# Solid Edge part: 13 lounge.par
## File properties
Author: Henri
Template: Normal.par
Last saved by: Henri
Revision: 5
Application: Solid Edge
Accuracy: 0,990
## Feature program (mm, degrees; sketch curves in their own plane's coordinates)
sketch for "unnamed Protrusion 1" plane through (0, 0, 0) normal (0, 0, 1) x-axis (1, 0, 0)
  line (82.5, -87.5) -> (-82.5, -87.5)
  line (-82.5, -87.5) -> (-82.5, 87.5)
  line (-82.5, 87.5) -> (82.5, 87.5)
  line (82.5, 87.5) -> (82.5, -87.5)
extrude "unnamed Protrusion 1" add finite 2.5 along -normal
sketch for "unnamed Cutout 1" plane through (0, 0, 0) normal (0, 0, 1) x-axis (1, 0, 0)
  line (-64, 72.5) -> (-45, 72.5)
  arc centre (-45, 83) radius 10.5 from (-45, 72.5) to (-34.5, 83) ccw
  line (-34.5, 83) -> (-34.5, 92)
  arc centre (-45, 92) radius 10.5 from (-34.5, 92) to (-45, 102.5) ccw
  line (-45, 102.5) -> (-64, 102.5)
  arc centre (-64, 92) radius 10.5 from (-64, 102.5) to (-74.5, 92) ccw
  line (-74.5, 92) -> (-74.5, 83)
  arc centre (-64, 83) radius 10.5 from (-74.5, 83) to (-64, 72.5) ccw
extrude "unnamed Cutout 1" cut through along -normal
sketch for "ExtrudedProtrusion_2" plane through (0, 0, 0) normal (0, 0, 1) x-axis (0, 1, 0)
  line (-87.5, -2.5) -> (-57.5, -2.5)
  arc centre (-57.5, -7.5) radius 5 from (-57.5, -2.5) to (-52.5, -7.5) cw
  line (-52.5, -7.5) -> (-52.5, -42.5)
  line (-52.5, -42.5) -> (-47.5, -47.5)
  line (-47.5, -47.5) -> (47.5, -47.5)
  line (52.5, -42.5) -> (47.5, -47.5)
  line (52.5, -42.5) -> (52.5, 22.5)
  arc centre (57.5, 22.5) radius 5 from (52.5, 22.5) to (57.5, 27.5) cw
  line (82.5, 27.5) -> (57.5, 27.5)
  arc centre (82.5, 22.5) radius 5 from (82.5, 27.5) to (87.5, 22.5) cw
  line (87.5, 22.5) -> (87.5, -82.5)
  line (-87.5, -82.5) -> (87.5, -82.5)
  line (-87.5, -2.5) -> (-87.5, -82.5)
extrude "ExtrudedProtrusion_2" add finite 37.5 along +normal
sketch for "ExtrudedCutout_2" plane through (27.5, 0, 37.5) normal (0, 0, 1) x-axis (0, 1, 0)
  line (77.5, 40) -> (77.5, -25.3553)
  line (57.8553, -45) -> (77.5, -25.3553)
  line (57.8553, -45) -> (-57.8553, -45)
  line (-77.5, -25.3553) -> (-57.8553, -45)
  line (-77.5, -25.3553) -> (-77.5, 10)
  arc centre (-72.5, 10) radius 5 from (-77.5, 10) to (-72.5, 15) cw
  line (-72.5, 15) -> (-50, 15)
  line (-50, 15) -> (-50, -13.9645)
  line (-50, -13.9645) -> (-46.4645, -17.5)
  line (-46.4645, -17.5) -> (46.4645, -17.5)
  line (46.4645, -17.5) -> (50, -13.9645)
  line (50, -13.9645) -> (50, 45)
  line (50, 45) -> (72.5, 45)
  arc centre (72.5, 40) radius 5 from (72.5, 45) to (77.5, 40) cw
extrude "ExtrudedCutout_2" cut finite 17.5 along -normal
fillet "Round_1" radius 2.5
sketch for "ExtrudedProtrusion_3" plane through (0, 0, 35) normal (0, 0, 1) x-axis (1, 0, 0)
  line (7.5, -37.5) -> (7.5, 7.5)
  arc centre (2.5, 7.5) radius 5 from (2.5, 12.5) to (7.5, 7.5) cw
  line (-17.5, 12.5) -> (2.5, 12.5)
  arc centre (-17.5, 17.5) radius 5 from (-22.5, 17.5) to (-17.5, 12.5) ccw
  line (-22.5, 37.5) -> (-22.5, 17.5)
  arc centre (-17.5, 37.5) radius 5 from (-22.5, 37.5) to (-17.5, 42.5) cw
  line (32.5, 42.5) -> (-17.5, 42.5)
  arc centre (32.5, 37.5) radius 5 from (37.5, 37.5) to (32.5, 42.5) ccw
  line (37.5, -37.5) -> (37.5, 37.5)
  arc centre (32.5, -37.5) radius 5 from (32.5, -42.5) to (37.5, -37.5) ccw
  line (12.5, -42.5) -> (32.5, -42.5)
  arc centre (12.5, -37.5) radius 5 from (7.5, -37.5) to (12.5, -42.5) ccw
extrude "ExtrudedProtrusion_3" add finite 2.5 along -normal
sketch for "ExtrudedProtrusion_4" #1 plane through (0, 0, 0) normal (0, 0, 1) x-axis (1, 0, 0)
  circle centre (22.5, -27.5) radius 3.75
sketch for "ExtrudedProtrusion_4" #2 plane through (0, 0, 0) normal (0, 0, 1) x-axis (1, 0, 0)
  circle centre (22.5, 27.5) radius 3.75
sketch for "ExtrudedProtrusion_4" #3 plane through (0, 0, 0) normal (0, 0, 1) x-axis (1, 0, 0)
  circle centre (-7.5, 27.5) radius 3.75
extrude "ExtrudedProtrusion_4" add finite 5 along +normal
sketch for "unnamed Protrusion 2" #1 plane through (22.5, -27.5, 5) normal (0, 0, 1) x-axis (0, 1, 0)
  circle centre (0, 0) radius 2.5
sketch for "unnamed Protrusion 2" #2 plane through (22.5, -27.5, 5) normal (0, 0, 1) x-axis (0, 1, 0)
  circle centre (55, 30) radius 2.5
sketch for "unnamed Protrusion 2" #3 plane through (22.5, -27.5, 5) normal (0, 0, 1) x-axis (0, 1, 0)
  circle centre (55, 0) radius 2.5
extrude "unnamed Protrusion 2" add through along +normal
fillet "Round_2" radius 1
sketch for "unnamed Cutout 2" plane through (-17.5, 0, 0) normal (0, 0, 1) x-axis (0, 1, 0)
  line (-87.5, 10) -> (82.5, 10)
  arc centre (82.5, 5) radius 5 from (82.5, 10) to (87.5, 5) cw
  line (87.5, 65) -> (87.5, 5)
  line (-87.5, 65) -> (87.5, 65)
  line (-87.5, 10) -> (-87.5, 65)
extrude "unnamed Cutout 2" cut through along -normal
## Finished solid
Body 1: solid body, 120 faces, 256 edges, 137 vertices.
  Faces by surface: cylinder 55, plane 32, torus 31, sphere 2
  Edges by curve: line 124, circle 120, ellipse 12
Bounding box of the edges (mm; curved faces can reach further): 110.000 x 175.000 x 40.000, from (-27.5, -87.5, -2.5) to (82.5, 87.5, 37.5).
Cylindrical faces by radius (mm): R1 x12, R2.5 x29, R3.75 x3, R5 x11
Toroidal faces (ring radius, tube radius in mm): R2.5 r2.5 x5, R2.75 r1 x3, R3.5 r1 x3, R4 r1 x10, R4.75 r1 x3, R5 r2.5 x3, R6 r1 x2, R7.5 r2.5 x2
Spherical faces by radius (mm): R2.5 x2
Planar faces by outward normal: +x 4, +y 4, +z 7, -x 6, -y 5, -z 2, oblique 4
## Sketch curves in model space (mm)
line (-34.5, 87.5, 0) -> (-22.5, 87.5, 0)
arc centre (-22.5, 82.5, 0) radius 5 from (-27.5, 82.5, 0) through (-25.9312, 86.1369, 0) to (-22.5, 87.5, 0)
line (-82.5, 87.5, 0) -> (-22.5, 87.5, 0)
line (-82.5, -87.5, 0) -> (-82.5, 87.5, 0)
line (-27.5, -87.5, 0) -> (-82.5, -87.5, 0)
line (-27.5, -87.5, 0) -> (-27.5, 82.5, 0)
circle centre (-7.5, 27.5, 5) radius 2.5
circle centre (22.5, 27.5, 5) radius 2.5
circle centre (22.5, -27.5, 5) radius 2.5
circle centre (22.5, -27.5, 0) radius 3.75
circle centre (22.5, 27.5, 0) radius 3.75
circle centre (-7.5, 27.5, 0) radius 3.75
line (-10.0116, -27.5, 0) -> (43.0498, -27.5, 0)
line (-44.051, 27.5, 0) -> (44.6517, 27.5, 0)
line (22.5, 48.356, 0) -> (22.5, -45.753, 0)
line (-7.5, 45.3525, 0) -> (-7.5, 5.9068, 0)
arc centre (32.5, -37.5, 35) radius 5 from (32.5, -42.5, 35) through (36.1369, -40.9312, 35) to (37.5, -37.5, 35)
line (37.5, -37.5, 35) -> (37.5, 37.5, 35)
arc centre (32.5, 37.5, 35) radius 5 from (37.5, 37.5, 35) through (35.9312, 41.1369, 35) to (32.5, 42.5, 35)
line (32.5, 42.5, 35) -> (-17.5, 42.5, 35)
arc centre (-17.5, 37.5, 35) radius 5 from (-22.5, 37.5, 35) through (-20.9312, 41.1369, 35) to (-17.5, 42.5, 35)
line (-22.5, 37.5, 35) -> (-22.5, 17.5, 35)
arc centre (-17.5, 17.5, 35) radius 5 from (-22.5, 17.5, 35) through (-20.9312, 13.8631, 35) to (-17.5, 12.5, 35)
line (-17.5, 12.5, 35) -> (2.5, 12.5, 35)
arc centre (2.5, 7.5, 35) radius 5 from (2.5, 12.5, 35) through (6.1369, 10.9312, 35) to (7.5, 7.5, 35)
line (7.5, -37.5, 35) -> (7.5, 7.5, 35)
arc centre (12.5, -37.5, 35) radius 5 from (7.5, -37.5, 35) through (9.0688, -41.1369, 35) to (12.5, -42.5, 35)
line (12.5, -42.5, 35) -> (32.5, -42.5, 35)
line (12.5, -50, 37.5) -> (41.4645, -50, 37.5)
line (41.4645, -50, 37.5) -> (45, -46.4645, 37.5)
line (45, -46.4645, 37.5) -> (45, 46.4645, 37.5)
line (45, 46.4645, 37.5) -> (41.4645, 50, 37.5)
line (41.4645, 50, 37.5) -> (-17.5, 50, 37.5)
line (-17.5, 50, 37.5) -> (-17.5, 72.5, 37.5)
arc centre (-12.5, 72.5, 37.5) radius 5 from (-17.5, 72.5, 37.5) through (-15.9312, 76.1369, 37.5) to (-12.5, 77.5, 37.5)
line (-12.5, 77.5, 37.5) -> (52.8553, 77.5, 37.5)
line (72.5, 57.8553, 37.5) -> (52.8553, 77.5, 37.5)
line (72.5, 57.8553, 37.5) -> (72.5, -57.8553, 37.5)
line (52.8553, -77.5, 37.5) -> (72.5, -57.8553, 37.5)
line (52.8553, -77.5, 37.5) -> (17.5, -77.5, 37.5)
arc centre (17.5, -72.5, 37.5) radius 5 from (17.5, -77.5, 37.5) through (13.8631, -75.9312, 37.5) to (12.5, -72.5, 37.5)
line (12.5, -72.5, 37.5) -> (12.5, -50, 37.5)
arc centre (7.5, -57.5, 0) radius 5 from (2.5, -57.5, 0) through (4.0688, -53.8631, 0) to (7.5, -52.5, 0)
line (7.5, -52.5, 0) -> (42.5, -52.5, 0)
line (42.5, -52.5, 0) -> (47.5, -47.5, 0)
line (47.5, -47.5, 0) -> (47.5, 47.5, 0)
line (42.5, 52.5, 0) -> (47.5, 47.5, 0)
line (42.5, 52.5, 0) -> (-22.5, 52.5, 0)
arc centre (-22.5, 57.5, 0) radius 5 from (-22.5, 52.5, 0) through (-26.1369, 54.0688, 0) to (-27.5, 57.5, 0)
line (-27.5, 82.5, 0) -> (-27.5, 57.5, 0)
arc centre (-22.5, 82.5, 0) radius 5 from (-27.5, 82.5, 0) through (-25.9312, 86.1369, 0) to (-22.5, 87.5, 0)
line (-22.5, 87.5, 0) -> (82.5, 87.5, 0)
line (82.5, -87.5, 0) -> (82.5, 87.5, 0)
line (2.5, -87.5, 0) -> (82.5, -87.5, 0)
line (2.5, -87.5, 0) -> (2.5, -57.5, 0)
line (82.5, 87.5, 0) -> (82.5, -87.5, 0)
line (82.5, -87.5, 0) -> (-82.5, -87.5, 0)
line (-82.5, -87.5, 0) -> (-82.5, 87.5, 0)
line (-82.5, 87.5, 0) -> (82.5, 87.5, 0)
arc centre (-64, 83, 0) radius 3 from (-67, 83, 0) through (-66.0587, 80.8179, 0) to (-64, 80, 0)
line (-64, 80, 0) -> (-45, 80, 0)
arc centre (-45, 83, 0) radius 3 from (-45, 80, 0) through (-42.8179, 80.9413, 0) to (-42, 83, 0)
line (-42, 83, 0) -> (-42, 92, 0)
arc centre (-45, 92, 0) radius 3 from (-42, 92, 0) through (-42.9413, 94.1821, 0) to (-45, 95, 0)
line (-45, 95, 0) -> (-64, 95, 0)
arc centre (-64, 92, 0) radius 3 from (-67, 92, 0) through (-66.0587, 94.1821, 0) to (-64, 95, 0)
line (-67, 92, 0) -> (-67, 83, 0)
arc centre (-64, 83, 0) radius 10.5 from (-74.5, 83, 0) through (-71.2055, 75.3626, 0) to (-64, 72.5, 0)
line (-64, 72.5, 0) -> (-45, 72.5, 0)
arc centre (-45, 83, 0) radius 10.5 from (-45, 72.5, 0) through (-37.3626, 75.7945, 0) to (-34.5, 83, 0)
line (-34.5, 83, 0) -> (-34.5, 92, 0)
arc centre (-45, 92, 0) radius 10.5 from (-34.5, 92, 0) through (-37.7945, 99.6374, 0) to (-45, 102.5, 0)
line (-45, 102.5, 0) -> (-64, 102.5, 0)
arc centre (-64, 92, 0) radius 10.5 from (-64, 102.5, 0) through (-71.6374, 99.2055, 0) to (-74.5, 92, 0)
line (-74.5, 92, 0) -> (-74.5, 83, 0)
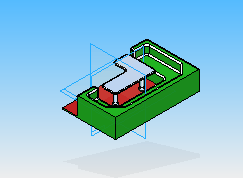
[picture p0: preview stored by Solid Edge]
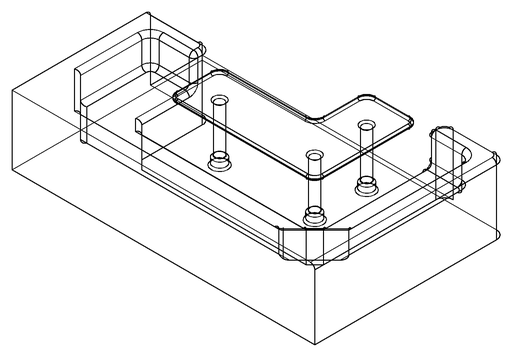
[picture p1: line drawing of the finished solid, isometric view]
